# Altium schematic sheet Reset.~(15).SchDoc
size A4
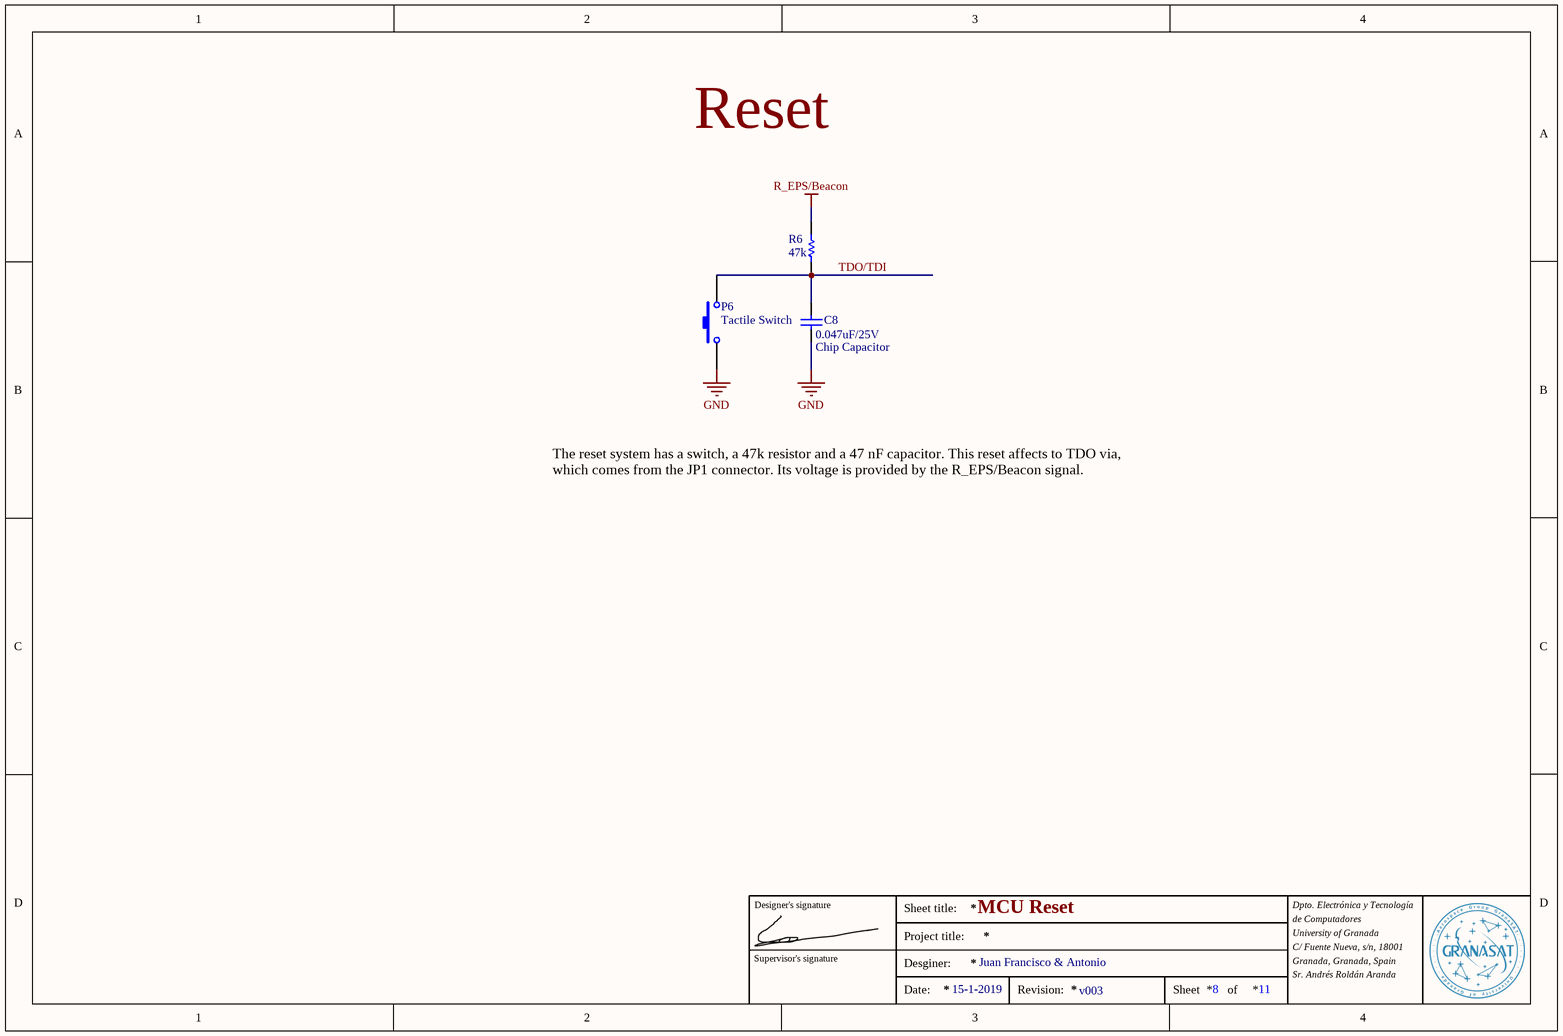
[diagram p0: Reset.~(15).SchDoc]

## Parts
C8  value 0.047uF/25V  PackageDescription: Chip Capacitor  [C0.047u]
P6  Tactile Switch  [SPST-2]
R6  47k  [R47k]

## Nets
GND: C8.2 P6.1
R_EPS/Beacon: R6.2
TDO/TDI: C8.1 P6.2 R6.1

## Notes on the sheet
- Reset
- The reset system has a switch, a 47k resistor and a 47 nF capacitor. This reset affects to TDO via, which comes from the JP1 connector. Its voltage is provided by the R_EPS/Beacon signal.
- Designer's signature
- Sheet title:
- MCU Reset
- Dpto. Electrónica y Tecnología
- de Computadores
- Supervisor's signature
- Project title:
- Desginer:
- Juan Francisco & Antonio
- University of Granada
- C/ Fuente Nueva, s/n, 18001
- Granada, Granada, Spain
- Sr. Andrés Roldán Aranda
- Date:
- 15-1-2019
- Revision:
- v003
- Sheet
- 8
- of
- 11

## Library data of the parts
C8 = Cap Semi: Capacitor (Semiconductor SIM Model)
P6 = SW-PB: Switch
R6 = Res1: Resistor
